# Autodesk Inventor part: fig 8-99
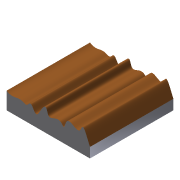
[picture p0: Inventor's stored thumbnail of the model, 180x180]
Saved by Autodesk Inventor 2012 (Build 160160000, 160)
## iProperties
Shininess: 64.0
Length Units: 11269
Angle Units: 11279
Time Units: 11290
Mass Units: 11283
Length Display Precision: 3
Angle Display Precision: 2
Compacted: True
Part Number: fig 8-99
Document SubType Name: Modeling
Created: 2002-12
Designer: deepak
Density: 1 g/cm^3
Material: Default
Density: 0.0
Volumn: 0.0
Area: 0.0
PropertySet Name: Model Information
Control State: 0
Master: False
Checked Out: False
Author: deepak
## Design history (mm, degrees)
sketch "Sketch1"
  geometry: L1 (-32.188, 30.089)-(27.812, 30.089); L2 (27.812, 30.089)-(27.812, -29.911); L3 (27.812, -29.911)-(-32.188, -29.911); L4 (-32.188, -29.911)-(-32.188, 30.089)
  constraints: 8 end point, 2 parallel, 1 horizontal, 1 perpendicular
  dimensions: "d0" = 60 distance of L1.start L1.end; "d1" = 60 distance of L3.end L1.start
extrude "Extrusion1" new body sketch "Sketch1" stored distance "d2" = 20; taper "d3" = 0 deg
sketch "Sketch2"
  geometry: 17 further points
  constraints: 17 other
extrude_surface "ExtrusionSrf1" sketch "Sketch2" dims "d4" = 70, "d5" = 0
split "Split1"
body "Solid1"
body "Srf1"
